(* Logix 5000 project; controller Test vendor 1 type 14 code 92 rev 30.11; software revision 30.00 *)

TASK MainTask (continuous, watchdog 500 ms) : MainProgram

MODULES
   Local : vendor 1 type 14 code 92 (ICP 0, rev 30.11)
      IN : vendor 1 type 7 code 1 (ICP 3, rev 3.2, Input RPI 20 ms)
      O : vendor 1 type 7 code 15 (ICP 2, rev 3.2, Output RPI 20 ms)
      Ethernet : 1756-ENBT (ICP 1, Ethernet 192.168.0.98, rev 6.4)
         Banner_ABR1 : vendor 12 type 43 code 410 (Ethernet 192.168.0.150, rev 1.4, StandardDataDriven RPI 50 ms)
END_MODULES

TYPE Banner_ABR_SMALL_IO_Data_Type :   // ABR AOI Data:
STRUCT
   InputBitsFromABR : SINT;   // The 8 bits used to receive the ABR's discrete output signals
   OutputBitsToABR : SINT;   // The 8 bits the ABR reads as inputs for control logic
   ItemStatus : INT;   // The current status code of the ABR
   FailureCode : SINT;   // The current failure code, if any. 0 = no failure.
   LastItemSeqNum : SINT;   // The 8-bit counter value for the last output message received from the ABR, goes up by 1 with each message received.
   LastItemData : STRING128;   // The last output message received from the ABR
END_STRUCT
END_TYPE

TYPE STRING128 :   // string type
STRUCT
   LEN : DINT;
   DATA : SINT[128];
END_STRUCT
END_TYPE

ADD_ON_INSTRUCTION Banner_ABR_AOI_SMALL_IO_Data   (* revision 1.0, vendor Banner Engineering *)
// AOI handles sequence number handshaking to put all the ABR barcode reader's implicit messaging data into named tags, including the latest output string, with a character limit of 128 characters.
// Help:
// The character limit of 128 was chosen because this is the maximum number of characters that the ABR can transmit over EtherNet/IP in one fragment or poll. Any remaining characters after the first 128 will be ignored.
VAR_IN_OUT
   RawDataFromABR : SINT[138]; {required}
   RawDataToABR : SINT[3]; {required}
   ABR_AOI_Tags : Banner_ABR_SMALL_IO_Data_Type; {required}
END_VAR
VAR
   PLC_LastFragSeqNum : SINT; {access None}   // The last fraqment number the PLC took in from the ABR.
   ABR_ItemSeqNum : SINT; {access None}   // The latest sequence number of the last item the ABR sent data for
   ABR_FragSeqNum : SINT; {access None}   // The last fragment sequence number of the data sent by the ABR
   ABR_FragDataSize : INT; {access None}   // The size of the last fragment sent by the ABR
END_VAR

ROUTINE Logic   (* ladder *)
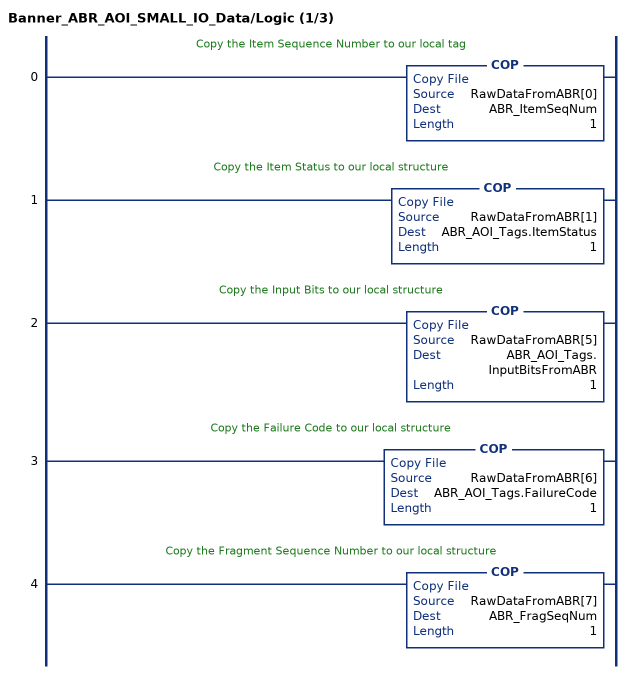
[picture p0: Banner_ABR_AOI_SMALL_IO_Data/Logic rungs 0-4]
   // Copy the Item Sequence Number to our local tag
   0: COP(RawDataFromABR[0],ABR_ItemSeqNum,1);
   // Copy the Item Status to our local structure
   1: COP(RawDataFromABR[1],ABR_AOI_Tags.ItemStatus,1);
   // Copy the Input Bits to our local structure
   2: COP(RawDataFromABR[5],ABR_AOI_Tags.InputBitsFromABR,1);
   // Copy the Failure Code to our local structure
   3: COP(RawDataFromABR[6],ABR_AOI_Tags.FailureCode,1);
   // Copy the Fragment Sequence Number to our local structure
   4: COP(RawDataFromABR[7],ABR_FragSeqNum,1);
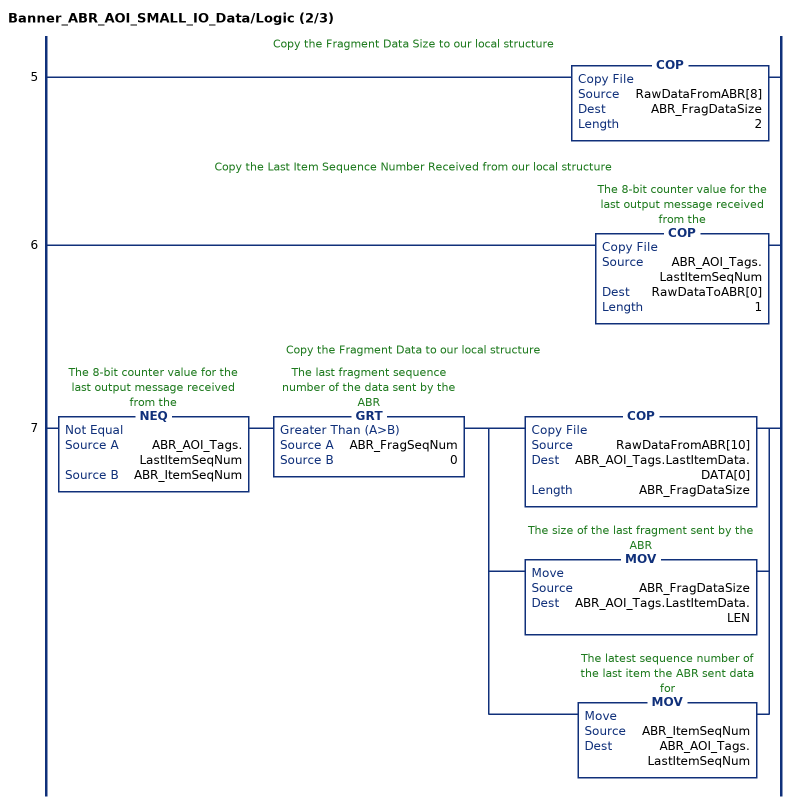
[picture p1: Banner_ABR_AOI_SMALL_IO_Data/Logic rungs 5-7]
   // Copy the Fragment Data Size to our local structure
   5: COP(RawDataFromABR[8],ABR_FragDataSize,2);
   // Copy the Last Item Sequence Number Received from our local structure
   6: COP(ABR_AOI_Tags.LastItemSeqNum,RawDataToABR[0],1);
   // Copy the Fragment Data to our local structure
   7: NEQ(ABR_AOI_Tags.LastItemSeqNum,ABR_ItemSeqNum)GRT(ABR_FragSeqNum,0)[COP(RawDataFromABR[10],ABR_AOI_Tags.LastItemData.DATA[0],ABR_FragDataSize) ,MOV(ABR_FragDataSize,ABR_AOI_Tags.LastItemData.LEN) ,MOV(ABR_ItemSeqNum,ABR_AOI_Tags.LastItemSeqNum) ];
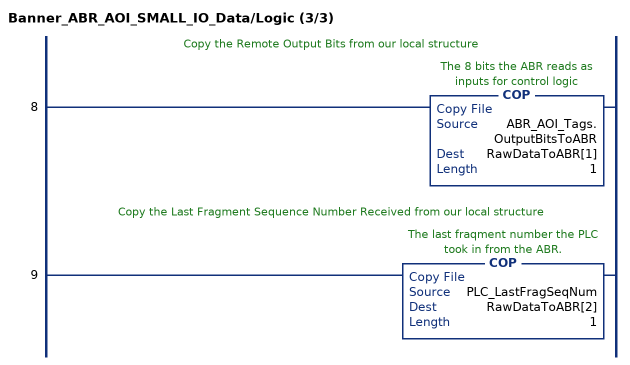
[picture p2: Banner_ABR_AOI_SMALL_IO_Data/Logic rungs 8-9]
   // Copy the Remote Output Bits from our local structure
   8: COP(ABR_AOI_Tags.OutputBitsToABR,RawDataToABR[1],1);
   // Copy the Last Fragment Sequence Number Received from our local structure
   9: COP(PLC_LastFragSeqNum,RawDataToABR[2],1);
END_ROUTINE
END_ADD_ON_INSTRUCTION

VAR_GLOBAL   (* controller tags *)
   Banner_ABR1_AOI : Banner_ABR_AOI_SMALL_IO_Data;
   Banner_ABR1_Tags : Banner_ABR_SMALL_IO_Data_Type;
END_VAR

PROGRAM MainProgram   (* main routine MainRoutine *)

ROUTINE MainRoutine   (* ladder *)
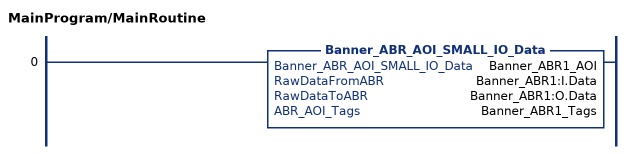
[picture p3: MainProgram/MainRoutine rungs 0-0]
   0: Banner_ABR_AOI_SMALL_IO_Data(Banner_ABR1_AOI,Banner_ABR1:I.Data,Banner_ABR1:O.Data,Banner_ABR1_Tags);
END_ROUTINE
END_PROGRAM
